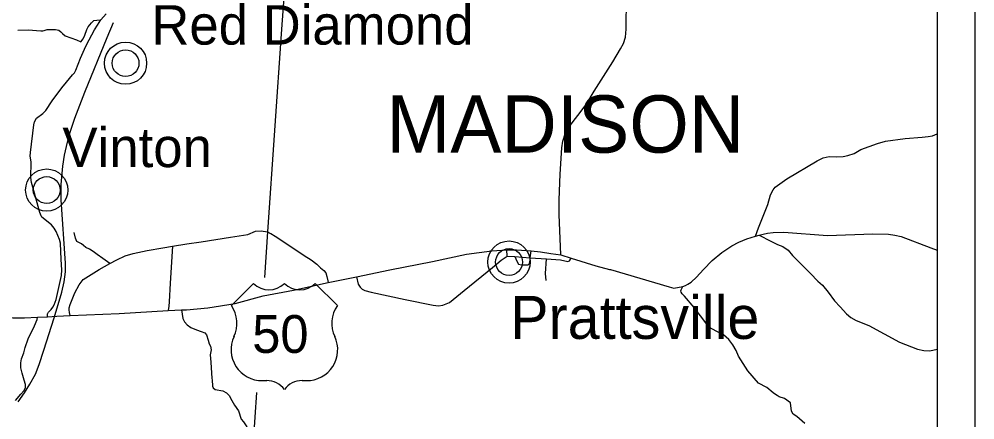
# Model space of a CAD drawing. Extents: x -22 to 431, y -18 to 160.
# Drawn here: x -17.504 to -14.978, y 25.005 to 26.065 of the extents above; entities that cross this region are included whole.
import ezdxf

# ---------------------------------------------------------------- set-up
doc = ezdxf.new("R2010")
doc.units = 0
for name, color, linetype in [('GM_X_Adjacent_County', 7, 'Continuous'), ('GM_X_Adjacent_County_Text', 7, 'Continuous'), ('GM_X_Airport_Location_Class_2', 7, 'Continuous'), ('GM_X_County_Road', 7, 'Continuous'), ('GM_X_County_Road_Text', 7, 'Continuous'), ('GM_X_County_ROW', 7, 'Continuous'), ('GM_X_Major_River_Text', 7, 'Continuous'), ('GM_X_Minor_River_Text', 7, 'Continuous'), ('GM_X_Section', 7, 'Continuous'), ('GM_X_State_Location', 7, 'Continuous'), ('GM_X_Township_Road', 7, 'Continuous'), ('GM_X_Township_ROW', 7, 'Continuous'), ('GM_X_Unincorporated_Location', 7, 'Continuous')]:
    doc.layers.add(name, color=color, linetype=linetype)

msp = doc.modelspace()

# ---------------------------------------------------------------- linework, layer by layer
at = {"layer": 'GM_X_Adjacent_County_Text'}
for points in [[(-15.5575, 25.4913), (-15.5492, 25.5132), (-15.525, 25.5751), (-15.5179, 25.6004), (-15.5111, 25.6135), (-15.5055, 25.6209), (-15.4745, 25.6429), (-15.3941, 25.6903), (-15.3782, 25.6982), (-15.363, 25.7016), (-15.3443, 25.7009), (-15.3261, 25.7019), (-15.3134, 25.7044), (-15.2966, 25.7097), (-15.279, 25.7198), (-15.2351, 25.7362), (-15.2142, 25.7418), (-15.1616, 25.7495), (-15.117, 25.753), (-15.1013, 25.7546), (-15.0892, 25.7565), (-15.0776, 25.7613)], [(-17.3684, 25.2814), (-17.3707, 25.2888), (-17.3718, 25.2959), (-17.3712, 25.3016), (-17.3686, 25.3101), (-17.3565, 25.3413), (-17.3452, 25.3626), (-17.3401, 25.3696), (-17.3341, 25.3761), (-17.3273, 25.381), (-17.2924, 25.4032), (-17.2637, 25.419), (-17.2454, 25.4284), (-17.2231, 25.4393), (-17.2021, 25.4449), (-17.1651, 25.4532), (-17.1239, 25.4605), (-17.0981, 25.4648), (-17.0602, 25.471), (-17.0225, 25.4757), (-16.9446, 25.4884), (-16.8991, 25.4954), (-16.8793, 25.504), (-16.8638, 25.5053), (-16.8469, 25.5028), (-16.8392, 25.4984)], [(-16.8392, 25.4984), (-16.8388, 25.4982), (-16.8268, 25.4909), (-16.8013, 25.4742), (-16.7499, 25.4399), (-16.7322, 25.428), (-16.7171, 25.4167), (-16.707, 25.4072), (-16.6984, 25.3999), (-16.6932, 25.3941), (-16.6903, 25.3847), (-16.688, 25.3731), (-16.687, 25.3685)], [(-15.5479, 25.4938), (-15.5167, 25.4774), (-15.4993, 25.4693), (-15.4856, 25.4635), (-15.4714, 25.4535), (-15.4596, 25.4402), (-15.4345, 25.4145), (-15.4122, 25.392), (-15.3929, 25.3721), (-15.3806, 25.3613), (-15.3653, 25.3428), (-15.3486, 25.3201), (-15.3335, 25.3039), (-15.3171, 25.2854), (-15.3054, 25.2754), (-15.2915, 25.2682), (-15.2578, 25.2547), (-15.1772, 25.2105), (-15.129, 25.1917), (-15.1123, 25.1883), (-15.0964, 25.1876), (-15.0776, 25.1918)], [(-16.6124, 25.3835), (-16.6078, 25.3636), (-16.6026, 25.3563), (-16.5968, 25.3505), (-16.59, 25.3469), (-16.5733, 25.3424), (-16.4836, 25.3237), (-16.4094, 25.3083), (-16.3951, 25.307), (-16.3834, 25.3085), (-16.3664, 25.3156), (-16.3273, 25.3473), (-16.2523, 25.408), (-16.2292, 25.4275), (-16.2137, 25.4377), (-16.1931, 25.4373), (-16.153, 25.4338), (-16.1102, 25.4311), (-16.073, 25.4282), (-16.0533, 25.424), (-16.0489, 25.4255), (-16.0443, 25.4325)], [(-17.513, 25.0561), (-17.4989, 25.0728), (-17.4908, 25.0822), (-17.4867, 25.0898), (-17.4871, 25.0983), (-17.49, 25.11), (-17.4957, 25.1286), (-17.499, 25.1426), (-17.4993, 25.1555), (-17.4976, 25.1667), (-17.4916, 25.1826), (-17.4875, 25.1961), (-17.4797, 25.2191), (-17.4632, 25.2536), (-17.4559, 25.2705), (-17.455, 25.2766)]]:
    msp.add_lwpolyline(points, dxfattribs=at)
at = {"layer": 'GM_X_County_Road'}
for points in [[(-17.5069, 26.0353), (-17.4797, 26.0369), (-17.4463, 26.0338), (-17.4411, 26.0338), (-17.4377, 26.0348), (-17.4326, 26.0366), (-17.4292, 26.0374), (-17.4255, 26.0377), (-17.4075, 26.0377), (-17.4031, 26.037), (-17.399, 26.0354), (-17.3936, 26.0315), (-17.3889, 26.0268), (-17.3819, 26.0206), (-17.3524, 26.0105), (-17.3402, 26.005), (-17.3347, 26.0131), (-17.3303, 26.0222), (-17.3245, 26.0371), (-17.3209, 26.0444), (-17.3128, 26.0548), (-17.3065, 26.0609), (-17.298, 26.0624), (-17.2875, 26.0627)], [(-17.2637, 25.419), (-17.2825, 25.4316), (-17.2973, 25.4428), (-17.3083, 25.4503), (-17.3176, 25.4567), (-17.3277, 25.4612), (-17.3332, 25.4665), (-17.3385, 25.4705), (-17.3455, 25.4744), (-17.3512, 25.4765), (-17.3548, 25.4854), (-17.3581, 25.5003)], [(-15.427, 24.9955), (-15.4481, 25.0136), (-15.4583, 25.0198), (-15.4622, 25.0284), (-15.4645, 25.0502), (-15.4812, 25.0617), (-15.4945, 25.066), (-15.5, 25.0695), (-15.5042, 25.0722)]]:
    msp.add_lwpolyline(points, dxfattribs=at)
at = {"layer": 'GM_X_County_ROW'}
for points in [[(-16.072, 25.4415), (-16.0759, 25.5481), (-16.0763, 25.5869), (-16.0736, 25.6552), (-16.0692, 25.7245), (-16.0665, 25.7425), (-16.0595, 25.7643), (-16.0518, 25.7777), (-16.0391, 25.7942), (-16.0209, 25.818), (-16.0036, 25.8421), (-15.9834, 25.874), (-15.9342, 25.9519), (-15.9142, 25.986), (-15.9067, 26.0008), (-15.9013, 26.017), (-15.8989, 26.0381), (-15.8984, 26.1218)], [(-17.4287, 25.2778), (-17.4288, 25.2829), (-17.4286, 25.2853), (-17.428, 25.2871), (-17.4272, 25.2883), (-17.4263, 25.2896), (-17.4192, 25.2972), (-17.4148, 25.303), (-17.4111, 25.309), (-17.408, 25.3168), (-17.406, 25.3238), (-17.3919, 25.3867), (-17.3911, 25.4021), (-17.3924, 25.4289), (-17.3946, 25.4727), (-17.3969, 25.4824), (-17.4057, 25.5035), (-17.4111, 25.5125), (-17.4183, 25.5212), (-17.4434, 25.5416), (-17.4457, 25.5447), (-17.4489, 25.5536), (-17.4629, 25.6046), (-17.471, 25.6328), (-17.4723, 25.6463), (-17.4722, 25.6863), (-17.4729, 25.6932), (-17.4742, 25.7025), (-17.474, 25.7123), (-17.465, 25.7858), (-17.4628, 25.7935), (-17.4575, 25.8027), (-17.4409, 25.8151), (-17.4329, 25.823), (-17.416, 25.8485), (-17.391, 25.8833), (-17.3786, 25.8984), (-17.3623, 25.9176), (-17.3573, 25.9232), (-17.3538, 25.9298), (-17.3414, 25.9614), (-17.3308, 25.9852), (-17.3253, 25.9966), (-17.3044, 26.0365), (-17.2965, 26.0494), (-17.2875, 26.0627), (-17.2732, 26.0788)], [(-15.943, 25.4031), (-15.941, 25.4026), (-15.7856, 25.3567), (-15.7736, 25.3538), (-15.7493, 25.3577), (-15.7422, 25.3608), (-15.7364, 25.3636), (-15.7274, 25.3692), (-15.7133, 25.3825), (-15.6948, 25.4032), (-15.6722, 25.4269), (-15.6464, 25.4481), (-15.6202, 25.4652), (-15.6011, 25.4751), (-15.5905, 25.4795), (-15.5799, 25.4841), (-15.5575, 25.4913), (-15.5479, 25.4938), (-15.5373, 25.4963), (-15.5255, 25.499), (-15.5109, 25.5009), (-15.4822, 25.5017), (-15.3672, 25.4931), (-15.2469, 25.4971), (-15.2057, 25.4965), (-15.1889, 25.4936), (-15.1725, 25.4899), (-15.0944, 25.4605), (-15.0776, 25.4535)], [(-17.4036, 25.2793), (-17.3684, 25.2814), (-17.2395, 25.2862), (-17.1098, 25.2942), (-17.0746, 25.2963), (-17.0615, 25.2962), (-17.0052, 25.3012), (-16.9326, 25.3132), (-16.8586, 25.3335), (-16.7789, 25.348), (-16.687, 25.3685), (-16.6124, 25.3835), (-16.5237, 25.4022), (-16.4109, 25.4236), (-16.3211, 25.4435), (-16.2542, 25.4525), (-16.2147, 25.4548), (-16.1894, 25.4546), (-16.1501, 25.4517), (-16.1256, 25.4494), (-16.0981, 25.445), (-16.072, 25.4415)], [(-16.072, 25.4415), (-16.0443, 25.4325), (-15.9791, 25.4124), (-15.943, 25.4031)], [(-17.5931, 25.291), (-17.5841, 25.2888), (-17.5693, 25.2853), (-17.5202, 25.2749), (-17.4895, 25.275), (-17.455, 25.2766), (-17.4287, 25.2778), (-17.4036, 25.2793)]]:
    msp.add_lwpolyline(points, dxfattribs=at)
at = {"layer": 'GM_X_Major_River_Text'}
for p, q in [((-16.7614, 26.707), (-16.8098, 26.0381)), ((-16.8098, 26.0381), (-16.8469, 25.5028)), ((-16.8469, 25.5028), (-16.8553, 25.3813)), ((-16.8764, 25.0773), (-16.8901, 24.8798))]:
    msp.add_line(p, q, dxfattribs=at)
at = {"layer": 'GM_X_Minor_River_Text'}
for points in [[(-17.0981, 25.4648), (-17.1045, 25.3664), (-17.107, 25.3175), (-17.1083, 25.3057), (-17.1098, 25.2942)], [(-16.1108, 25.3741), (-16.1125, 25.392), (-16.1102, 25.4311)], [(-15.5042, 25.0722), (-15.5108, 25.0766), (-15.5274, 25.0908), (-15.5496, 25.1023), (-15.5774, 25.135), (-15.6025, 25.1734), (-15.6086, 25.1886), (-15.617, 25.2037), (-15.6275, 25.2173), (-15.6421, 25.2298), (-15.6611, 25.2396), (-15.679, 25.2491), (-15.6862, 25.2583), (-15.7193, 25.3026), (-15.7448, 25.3319), (-15.7509, 25.3385), (-15.7537, 25.3427), (-15.7549, 25.3465), (-15.7543, 25.3493), (-15.7493, 25.3577)], [(-17.0746, 25.2963), (-17.0724, 25.2844), (-17.0706, 25.2735), (-17.0664, 25.2646), (-17.0598, 25.2564), (-17.0499, 25.2491), (-17.0353, 25.2433), (-17.0224, 25.2388), (-17.0131, 25.235), (-17.0084, 25.2297), (-17.0044, 25.2159), (-17.0011, 25.2066), (-16.9979, 25.1996), (-16.9965, 25.1905), (-16.9985, 25.1769), (-16.9973, 25.1579), (-16.994, 25.1147)], [(-16.994, 25.1147), (-16.9938, 25.1113), (-16.9925, 25.0942), (-16.9906, 25.0897), (-16.9852, 25.0852), (-16.9654, 25.0815), (-16.9559, 25.077), (-16.9481, 25.0694), (-16.9416, 25.0567), (-16.934, 25.0439), (-16.9241, 25.0289), (-16.9168, 25.0066), (-16.9103, 24.9996), (-16.9015, 24.987), (-16.8973, 24.9753), (-16.8991, 24.9627), (-16.8999, 24.9569)]]:
    msp.add_lwpolyline(points, dxfattribs=at)
at = {"layer": 'GM_X_Section'}
for p, q in [((-14.9776, 29.1642), (-14.9776, 22.1642)), ((-15.0776, 29.0642), (-15.0776, 22.2642)), ((-15.0776, 29.0642), (-15.0776, 22.2642))]:
    msp.add_line(p, q, dxfattribs=at)
at = {"layer": 'GM_X_State_Location'}
msp.add_lwpolyline([(-17.5066, 25.0531), (-17.4894, 25.0764), (-17.4758, 25.0996), (-17.4608, 25.1259), (-17.4507, 25.1514), (-17.4382, 25.1898), (-17.4114, 25.2751), (-17.3908, 25.3427), (-17.3845, 25.3701), (-17.3813, 25.3964), (-17.381, 25.4191), (-17.393, 25.5871), (-17.3927, 25.6272), (-17.3884, 25.6763), (-17.3841, 25.7052), (-17.3761, 25.7399), (-17.3691, 25.7661), (-17.3562, 25.8028), (-17.3296, 25.8718), (-17.2712, 26.0164), (-17.2546, 26.0563)], dxfattribs=at)
at = {"layer": 'GM_X_Township_Road'}
for centre, radius in [((-17.2224, 25.9484), 0.0558), ((-17.2224, 25.9484), 0.0354), ((-17.4308, 25.613), 0.0558), ((-17.4308, 25.613), 0.0354), ((-16.2089, 25.4225), 0.0558), ((-16.2089, 25.4225), 0.0354)]:
    msp.add_circle(centre, radius, dxfattribs=at)
at = {"layer": 'GM_X_Township_ROW'}
for points in [[(-16.2137, 25.4377), (-16.2147, 25.4548)], [(-16.153, 25.4338), (-16.1501, 25.4517)], [(-16.1931, 25.4373), (-16.1879, 25.4244), (-16.1835, 25.4167), (-16.1763, 25.4151), (-16.1652, 25.4149), (-16.158, 25.4149), (-16.1547, 25.4182), (-16.1534, 25.4273), (-16.153, 25.4338)]]:
    msp.add_lwpolyline(points, dxfattribs=at)
at = {"layer": 'GM_X_Unincorporated_Location'}
for p, q in [((-16.8843, 25.3658), (-16.9426, 25.3074)), ((-16.6625, 25.3074), (-16.7209, 25.3658)), ((-16.8609, 25.109), (-16.8493, 25.109)), ((-16.7559, 25.109), (-16.7442, 25.109))]:
    msp.add_line(p, q, dxfattribs=at)
for centre, radius, start, end in [((-16.8434, 25.4075), 0.0584, 225.573, 314.427), ((-16.7617, 25.4075), 0.0584, 225.573, 314.427), ((-17.0096, 25.2606), 0.0817, 334.5471, 35.0009), ((-16.5956, 25.2606), 0.0817, 144.9991, 205.4529), ((-16.8618, 25.1907), 0.0817, 154.8319, 270.6383), ((-16.7433, 25.1907), 0.0817, 269.3617, 25.1681), ((-16.8493, 25.0506), 0.0584, 36.8699, 90), ((-16.7559, 25.0506), 0.0584, 90, 143.1301)]:
    msp.add_arc(centre, radius, start, end, dxfattribs=at)

# ---------------------------------------------------------------- texts
at = {"layer": 'GM_X_Adjacent_County'}
for s, height, p in [('Red Diamond', 0.104167, (-17.1543, 25.9976)), ('Vinton', 0.10417, (-17.3892, 25.6735)), ('Prattsville', 0.113636, (-16.2058, 25.2192))]:
    msp.add_text(s, height=height, rotation=0, dxfattribs=at).set_placement(p)
at = {"layer": 'GM_X_Airport_Location_Class_2'}
msp.add_text('50', height=0.1, dxfattribs=at).set_placement((-16.8875, 25.1822))
at = {"layer": 'GM_X_County_Road_Text'}
msp.add_text('MADISON', height=0.15152, rotation=0, dxfattribs=at).set_placement((-16.5328, 25.7118))

doc.saveas('drawing.dxf')
